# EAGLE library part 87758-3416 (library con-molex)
34 Pin - 2mm Dual Row Single Wafer, Vertical T/H HDR Source: http://www.molex.com/pdm_docs/sd/877580616_sd.pdf
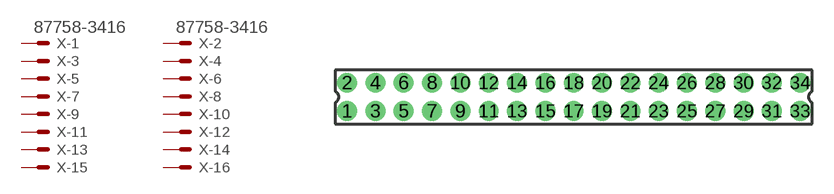
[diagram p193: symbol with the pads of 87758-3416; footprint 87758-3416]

Designator prefix X; gates -1=MV -2=MV -3=M -4=M -5=M -6=M -7=M -8=M -9=M -10=M -11=M -12=M -13=M -14=M -15=M -16=M -17=M -18=M -19=M -20=M -21=M -22=M -23=M -24=M -25=M -26=M -27=M -28=M -29=M -30=M -31=M -32=M -33=M -34=M

## 87758-3416 (MPN: 87758-3416; OC_FARNELL: unknown; OC_NEWARK: 25M5686)  [87758-3416]
1  -1:S  pas
2  -2:S  pas
3  -3:S  pas
4  -4:S  pas
5  -5:S  pas
6  -6:S  pas
7  -7:S  pas
8  -8:S  pas
9  -9:S  pas
10  -10:S  pas
11  -11:S  pas
12  -12:S  pas
13  -13:S  pas
14  -14:S  pas
15  -15:S  pas
16  -16:S  pas
17  -17:S  pas
18  -18:S  pas
19  -19:S  pas
20  -20:S  pas
21  -21:S  pas
22  -22:S  pas
23  -23:S  pas
24  -24:S  pas
25  -25:S  pas
26  -26:S  pas
27  -27:S  pas
28  -28:S  pas
29  -29:S  pas
30  -30:S  pas
31  -31:S  pas
32  -32:S  pas
33  -33:S  pas
34  -34:S  pas

## Footprint 87758-3416 (pad centres in mm)
34 Pin - 2mm Dual Row Single Wafer, Vertical T/H HDR Source: http://www.molex.com/pdm_docs/sd/877580616_sd.pdf
drill 0.9 pad 1.27 round: 1 -16,-1; 2 -16,1; 3 -14,-1; 4 -14,1; 5 -12,-1; 6 -12,1; 7 -10,-1; 8 -10,1; 9 -8,-1; 10 -8,1; 11 -6,-1; 12 -6,1; 13 -4,-1; 14 -4,1; 15 -2,-1; 16 -2,1; 17 0,-1; 18 0,1; 19 2,-1; 20 2,1; 21 4,-1; 22 4,1; 23 6,-1; 24 6,1; 25 8,-1; 26 8,1; 27 10,-1; 28 10,1; 29 12,-1; 30 12,1; 31 14,-1; 32 14,1; 33 16,-1; 34 16,1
